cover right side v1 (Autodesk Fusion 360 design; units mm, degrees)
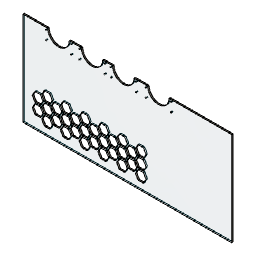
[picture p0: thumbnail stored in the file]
sketch "Sketch1" plane through (0, 0, 0) normal (0, 1, 0) x axis (1, 0, 0)
  line L1 (-390, 175) -> (-390, -175)
  line L2 (390, 175) -> (-390, 175)
  line L3 (390, -175) -> (390, 175)
  line L4 (156, -175) -> (390, -175)
  line L5 (-297, -175) -> (-390, -175)
  line L6 (-172, -175) -> (-217, -175)
  line L7 (-55, -175) -> (-92, -175)
  line L8 (76, -175) -> (25, -175)
  line L9 (-289.9919, 32.6935) -> (-309.9919, 32.6842)
  line L10 (-280, 50.0187) -> (-289.9919, 32.6935)
  line L11 (-290.0081, 67.3345) -> (-280, 50.0187)
  line L12 (-310.0081, 67.3252) -> (-290.0081, 67.3345)
  line L13 (-320, 50) -> (-310.0081, 67.3252)
  line L14 (-309.9919, 32.6842) -> (-320, 50)
  line L15 (-290.0081, 67.3345) -> (-280, 50.0187)
  line L16 (-280, 50.0187) -> (-289.9919, 32.6935)
  line L17 (-310.0081, 67.3252) -> (-290.0081, 67.3345)
  line L18 (-309.9919, 32.6842) -> (-320, 50)
  line L19 (-289.9919, 32.6935) -> (-309.9919, 32.6842)
  line L20 (-320, 50) -> (-310.0081, 67.3252)
  line L21 (-290.0081, 107.3345) -> (-280, 90.0187)
  line L22 (-280, 90.0187) -> (-289.9919, 72.6935)
  line L23 (-310.0081, 107.3252) -> (-290.0081, 107.3345)
  line L24 (-309.9919, 72.6842) -> (-320, 90)
  line L25 (-289.9919, 72.6935) -> (-309.9919, 72.6842)
  line L26 (-320, 90) -> (-310.0081, 107.3252)
  line L27 (-255.0081, 87.3345) -> (-245, 70.0187)
  line L28 (-245, 70.0187) -> (-254.9919, 52.6935)
  line L29 (-275.0081, 87.3252) -> (-255.0081, 87.3345)
  line L30 (-274.9919, 52.6842) -> (-285, 70)
  line L31 (-254.9919, 52.6935) -> (-274.9919, 52.6842)
  line L32 (-285, 70) -> (-275.0081, 87.3252)
  line L33 (-240.0081, 67.3252) -> (-220.0081, 67.3345)
  line L34 (-219.9919, 32.6935) -> (-239.9919, 32.6842)
  line L35 (-210, 50.0187) -> (-219.9919, 32.6935)
  line L36 (-219.9919, 72.6935) -> (-239.9919, 72.6842)
  line L37 (-175, 70.0187) -> (-184.9919, 52.6935)
  line L38 (-184.9919, 52.6935) -> (-204.9919, 52.6842)
  line L39 (-240.0081, 67.3252) -> (-220.0081, 67.3345)
  line L40 (-215, 70) -> (-205.0081, 87.3252)
  line L41 (-239.9919, 72.6842) -> (-250, 90)
  line L42 (-240.0081, 107.3252) -> (-220.0081, 107.3345)
  line L43 (-239.9919, 32.6842) -> (-250, 50)
  line L44 (-220.0081, 107.3345) -> (-210, 90.0187)
  line L45 (-185.0081, 87.3345) -> (-175, 70.0187)
  line L46 (-210, 90.0187) -> (-219.9919, 72.6935)
  line L47 (-250, 50) -> (-240.0081, 67.3252)
  line L48 (-204.9919, 52.6842) -> (-215, 70)
  line L49 (-220.0081, 67.3345) -> (-210, 50.0187)
  line L50 (-205.0081, 87.3252) -> (-185.0081, 87.3345)
  line L51 (-210, 50.0187) -> (-219.9919, 32.6935)
  line L52 (-250, 50) -> (-240.0081, 67.3252)
  line L53 (-220.0081, 67.3345) -> (-210, 50.0187)
  line L54 (-219.9919, 32.6935) -> (-239.9919, 32.6842)
  line L55 (-250, 90) -> (-240.0081, 107.3252)
  line L56 (-239.9919, 32.6842) -> (-250, 50)
  line L57 (-170.0081, 67.3252) -> (-150.0081, 67.3345)
  line L58 (-149.9919, 32.6935) -> (-169.9919, 32.6842)
  line L59 (-140, 50.0187) -> (-149.9919, 32.6935)
  line L60 (-149.9919, 72.6935) -> (-169.9919, 72.6842)
  line L61 (-105, 70.0187) -> (-114.9919, 52.6935)
  line L62 (-114.9919, 52.6935) -> (-134.9919, 52.6842)
  line L63 (-170.0081, 67.3252) -> (-150.0081, 67.3345)
  line L64 (-145, 70) -> (-135.0081, 87.3252)
  line L65 (-169.9919, 72.6842) -> (-180, 90)
  line L66 (-170.0081, 107.3252) -> (-150.0081, 107.3345)
  line L67 (-169.9919, 32.6842) -> (-180, 50)
  line L68 (-150.0081, 107.3345) -> (-140, 90.0187)
  line L69 (-115.0081, 87.3345) -> (-105, 70.0187)
  line L70 (-140, 90.0187) -> (-149.9919, 72.6935)
  line L71 (-180, 50) -> (-170.0081, 67.3252)
  line L72 (-134.9919, 52.6842) -> (-145, 70)
  line L73 (-150.0081, 67.3345) -> (-140, 50.0187)
  line L74 (-135.0081, 87.3252) -> (-115.0081, 87.3345)
  line L75 (-140, 50.0187) -> (-149.9919, 32.6935)
  line L76 (-180, 50) -> (-170.0081, 67.3252)
  line L77 (-150.0081, 67.3345) -> (-140, 50.0187)
  line L78 (-149.9919, 32.6935) -> (-169.9919, 32.6842)
  line L79 (-180, 90) -> (-170.0081, 107.3252)
  line L80 (-169.9919, 32.6842) -> (-180, 50)
  line L81 (-315, 70.0187) -> (-324.9919, 52.6935)
  line L82 (-324.9919, 52.6935) -> (-344.9919, 52.6842)
  line L83 (-355, 70) -> (-345.0081, 87.3252)
  line L84 (-325.0081, 87.3345) -> (-315, 70.0187)
  line L85 (-344.9919, 52.6842) -> (-355, 70)
  line L86 (-345.0081, 87.3252) -> (-325.0081, 87.3345)
  line L87 (-100.0081, 67.3252) -> (-80.0081, 67.3345)
  line L88 (-79.9919, 32.6935) -> (-99.9919, 32.6842)
  line L89 (-70, 50.0187) -> (-79.9919, 32.6935)
  line L90 (-79.9919, 72.6935) -> (-99.9919, 72.6842)
  line L91 (-35, 70.0187) -> (-44.9919, 52.6935)
  line L92 (-44.9919, 52.6935) -> (-64.9919, 52.6842)
  line L93 (-100.0081, 67.3252) -> (-80.0081, 67.3345)
  line L94 (-75, 70) -> (-65.0081, 87.3252)
  line L95 (-99.9919, 72.6842) -> (-110, 90)
  line L96 (-100.0081, 107.3252) -> (-80.0081, 107.3345)
  line L97 (-99.9919, 32.6842) -> (-110, 50)
  line L98 (-80.0081, 107.3345) -> (-70, 90.0187)
  line L99 (-45.0081, 87.3345) -> (-35, 70.0187)
  line L100 (-70, 90.0187) -> (-79.9919, 72.6935)
  line L101 (-110, 50) -> (-100.0081, 67.3252)
  line L102 (-64.9919, 52.6842) -> (-75, 70)
  line L103 (-80.0081, 67.3345) -> (-70, 50.0187)
  line L104 (-65.0081, 87.3252) -> (-45.0081, 87.3345)
  line L105 (-70, 50.0187) -> (-79.9919, 32.6935)
  line L106 (-110, 50) -> (-100.0081, 67.3252)
  line L107 (-80.0081, 67.3345) -> (-70, 50.0187)
  line L108 (-79.9919, 32.6935) -> (-99.9919, 32.6842)
  line L109 (-110, 90) -> (-100.0081, 107.3252)
  line L110 (-99.9919, 32.6842) -> (-110, 50)
  line L111 (-30.0081, 67.3252) -> (-10.0081, 67.3345)
  line L112 (-9.9919, 32.6935) -> (-29.9919, 32.6842)
  line L113 (0, 50.0187) -> (-9.9919, 32.6935)
  line L114 (-9.9919, 72.6935) -> (-29.9919, 72.6842)
  line L115 (35, 70.0187) -> (25.0081, 52.6935)
  line L116 (25.0081, 52.6935) -> (5.0081, 52.6842)
  line L117 (-30.0081, 67.3252) -> (-10.0081, 67.3345)
  line L118 (-5, 70) -> (4.9919, 87.3252)
  line L119 (-29.9919, 72.6842) -> (-40, 90)
  line L120 (-30.0081, 107.3252) -> (-10.0081, 107.3345)
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  point P2 (-390, -175)
  point P3 (-390, 175)
  point P4 (390, 175)
  point P1 (0, 0)
  point P7 (-297, -175)
  point P8 (-217, -175)
  point P9 (-172, -175)
  point P10 (-92, -175)
  point P11 (-55, -175)
  point P12 (25, -175)
  point P6 (156, -175)
  point P13 (76, -175)
  point P5 (390, -175)
  point P18 (-309.9919, 32.6842)
  point P19 (-289.9919, 32.6935)
  point P26 (-289.9919, 32.6935)
  point P28 (-309.9919, 32.6842)
  point P34 (-289.9919, 72.6935)
  point P36 (-309.9919, 72.6842)
  point P42 (-254.9919, 52.6935)
  point P44 (-274.9919, 52.6842)
  point P50 (-219.9919, 32.6935)
  point P52 (-239.9919, 32.6842)
  point P59 (-239.9919, 32.6842)
  point P64 (-219.9919, 32.6935)
  point P75 (-239.9919, 72.6842)
  point P78 (-219.9919, 72.6935)
  point P71 (-204.9919, 52.6842)
  point P73 (-184.9919, 52.6935)
  point P82 (-149.9919, 32.6935)
  point P84 (-169.9919, 32.6842)
  point P91 (-169.9919, 32.6842)
  point P96 (-149.9919, 32.6935)
  point P107 (-169.9919, 72.6842)
  point P110 (-149.9919, 72.6935)
  point P103 (-134.9919, 52.6842)
  point P105 (-114.9919, 52.6935)
  point P119 (-344.9919, 52.6842)
  point P121 (-324.9919, 52.6935)
  point P122 (-79.9919, 32.6935)
  point P124 (-99.9919, 32.6842)
  point P131 (-99.9919, 32.6842)
  point P136 (-79.9919, 32.6935)
  point P147 (-99.9919, 72.6842)
  point P150 (-79.9919, 72.6935)
  point P143 (-64.9919, 52.6842)
  point P145 (-44.9919, 52.6935)
  point P154 (-9.9919, 32.6935)
  point P156 (-29.9919, 32.6842)
  point P163 (-29.9919, 32.6842)
  point P168 (-9.9919, 32.6935)
  point P179 (-29.9919, 72.6842)
  point P182 (-9.9919, 72.6935)
  point P175 (5.0081, 52.6842)
  point P177 (25.0081, 52.6935)
  point P186 (60.0081, 32.6935)
  point P188 (40.0081, 32.6842)
  point P195 (40.0081, 32.6842)
  point P200 (60.0081, 32.6935)
  point P203 (40.0081, 72.6842)
  point P206 (60.0081, 72.6935)
  point P210 (-324.9919, 92.6935)
  point P212 (-344.9919, 92.6842)
  point P221 (-344.9919, 92.6842)
  point P226 (-324.9919, 92.6935)
  point P245 (-309.9919, 112.6842)
  point P247 (-289.9919, 112.6935)
  point P270 (-274.9919, 92.6842)
  point P273 (-254.9919, 92.6935)
  point P229 (-254.9919, 92.6935)
  point P253 (-274.9919, 92.6842)
  point P295 (-239.9919, 112.6842)
  point P296 (-219.9919, 112.6935)
  point P332 (-184.9919, 92.6935)
  point P338 (-204.9919, 92.6842)
  point P290 (-184.9919, 92.6935)
  point P336 (-204.9919, 92.6842)
  point P283 (-169.9919, 112.6842)
  point P285 (-149.9919, 112.6935)
  point P218 (-114.9919, 92.6935)
  point P324 (-134.9919, 92.6842)
  point P260 (-114.9919, 92.6935)
  point P320 (-134.9919, 92.6842)
  point P274 (-99.9919, 112.6842)
  point P277 (-79.9919, 112.6935)
  point P234 (-44.9919, 92.6935)
  point P236 (-64.9919, 92.6842)
  point P342 (-64.9919, 92.6842)
  point P352 (-44.9919, 92.6935)
  point P300 (-29.9919, 112.6842)
  point P301 (-9.9919, 112.6935)
  point P262 (25.0081, 92.6935)
  point P265 (5.0081, 92.6842)
  point P305 (5.0081, 92.6842)
  point P307 (25.0081, 92.6935)
  point P327 (60.0081, 112.6935)
  point P329 (40.0081, 112.6842)
  point P354 (-304, -167)
  point P355 (-304, -133)
  vertical L1
  perpendicular L1 L2
  perpendicular L2 L3
  perpendicular L1 L5
  parallel L5 L6
  parallel L6 L7
  parallel L7 L8
  dimension "d1" distance P2 P3 = 350
  dimension "d2" distance P3 P4 = 780
  dimension "d3" distance P1 L1 = 390 (= "( 780 / 2 ) * 1 mm")
  dimension "d4" distance P1 L2 = 175 (= "( 350 / 2 ) * 1 mm")
  dimension "d5" distance P2 P7 = 93
  dimension "d8" distance P7 P8 = 80
  dimension "d10" distance P9 P10 = 80
  dimension "d12" distance P11 P12 = 80
  dimension "d13" distance P6 P13 = 80
  dimension "d14" distance P8 P9 = 45
  dimension "d15" distance P10 P11 = 37
  dimension "d16" distance P12 P13 = 51
  dimension "d17" distance P5 P6 = 234
  dimension "d23" distance P18 P19 = 20
  dimension "d24" distance P26 P28 = 20
  dimension "d25" distance P34 P36 = 20
  dimension "d26" distance P42 P44 = 20
  dimension "d27" distance P50 P52 = 20
  dimension "d28" distance P59 P64 = 20
  dimension "d29" distance P75 P78 = 20
  dimension "d30" distance P71 P73 = 20
  dimension "d31" distance P82 P84 = 20
  dimension "d32" distance P91 P96 = 20
  dimension "d33" distance P107 P110 = 20
  dimension "d34" distance P103 P105 = 20
  dimension "d38" distance P119 P121 = 20
  dimension "d39" distance P122 P124 = 20
  dimension "d40" distance P131 P136 = 20
  dimension "d41" distance P147 P150 = 20
  dimension "d42" distance P143 P145 = 20
  dimension "d43" distance P154 P156 = 20
  dimension "d44" distance P163 P168 = 20
  dimension "d45" distance P179 P182 = 20
  dimension "d46" distance P175 P177 = 20
  dimension "d47" distance P186 P188 = 20
  dimension "d48" distance P195 P200 = 20
  dimension "d49" distance P203 P206 = 20
  dimension "d51" distance P210 P212 = 20
  dimension "d52" distance P221 P226 = 20
  dimension "d54" distance P245 P247 = 20
  dimension "d55" distance P270 P273 = 20
  dimension "d56" distance P229 P253 = 20
  dimension "d58" distance P295 P296 = 20
  dimension "d59" distance P332 P338 = 20
  dimension "d60" distance P290 P336 = 20
  dimension "d62" distance P283 P285 = 20
  dimension "d64" distance P218 P324 = 20
  dimension "d65" distance P260 P320 = 20
  dimension "d67" distance P274 P277 = 20
  dimension "d68" distance P234 P236 = 20
  dimension "d69" distance P342 P352 = 20
  dimension "d71" distance P300 P301 = 20
  dimension "d72" distance P262 P265 = 20
  dimension "d73" distance P305 P307 = 20
  dimension "d75" distance P327 P329 = 20
  dimension "d81" diameter = 4
  dimension "d82" distance P7 P354 = 7
  dimension "d83" distance L5 P354 = 8
  dimension "d84" diameter = 4
  dimension "d85" distance L5 P355 = 42 (= "34 mm + 8 mm")
  dimension "d86" diameter = 4
  dimension "d87" diameter = 4
  dimension "d88" diameter = 4
  dimension "d89" diameter = 4
  dimension "d90" diameter = 4
  dimension "d91" diameter = 4
  dimension "d92" diameter = 4
  dimension "d93" diameter = 4
  dimension "d94" diameter = 4
  dimension "d95" diameter = 4
  dimension "d96" diameter = 4
  dimension "d97" diameter = 4
  dimension "d98" diameter = 4
  dimension "d99" diameter = 4
extrude "Extrude2" new body sketch "Sketch1" along normal blind 5
extrude "Extrude1" new body sketch "Sketch1" along normal blind 5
